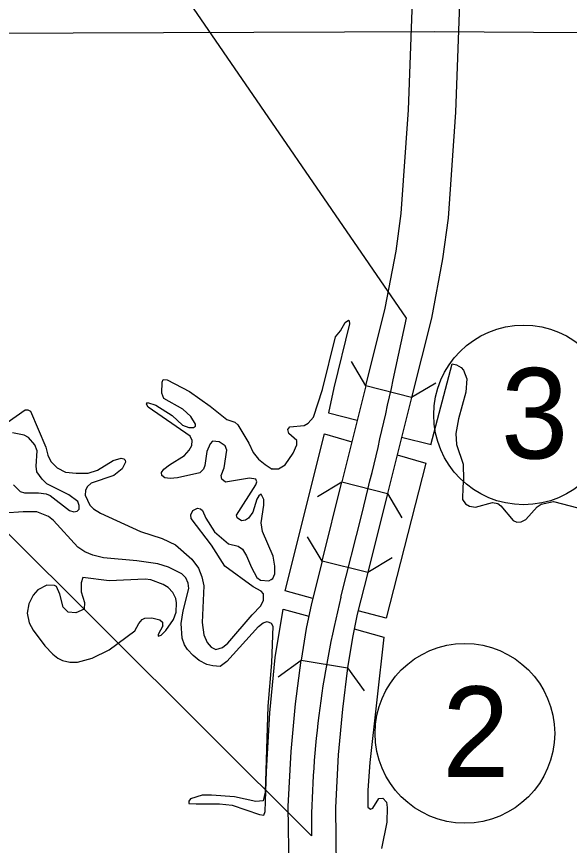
# Model space of a CAD drawing. Extents: x 982240 to 1103002, y 974866 to 1054902.
# Drawn here: x 1025635 to 1028568, y 1003474 to 1007871 of the extents above; entities that cross this region are included whole.
import ezdxf

# ---------------------------------------------------------------- set-up
doc = ezdxf.new("R2010")
doc.units = 0
for name, color, linetype in [('15', 7, 'Continuous'), ('35', 7, 'Continuous'), ('37', 7, 'Continuous'), ('5', 7, 'Continuous'), ('9', 7, 'Continuous'), ('Level 8', 7, 'Continuous'), ('R_Draft', 7, 'Continuous')]:
    doc.layers.add(name, color=color, linetype=linetype)

msp = doc.modelspace()

# ---------------------------------------------------------------- linework, layer by layer
at = {"layer": '15'}
for p, q in [((1027730.2, 1005850.2), (1027488, 1005912.1)), ((1027360.4, 1005402.5), (1027602.6, 1005340.5)), ((1027498, 1004922.3), (1027255.4, 1004983)), ((1027144.1, 1004456.7), (1027390.8, 1004416.4))]:
    msp.add_line(p, q, dxfattribs=at)
for points in [[(1027488, 1005912.1), (1027591.2, 1006324.5), (1027648, 1006626.3), (1027675.6, 1006826.9), (1027714.1, 1007377.1), (1027837.7, 1010743.3), (1027884.1, 1012159.8), (1027883.1, 1012543.8), (1027847.3, 1013534.7), (1027848.2, 1013935.1), (1027894.2, 1014987.8), (1027946.2, 1016469.3)], [(1028196.1, 1016460.3), (1028144, 1014978), (1028098.2, 1013929.3), (1028097.3, 1013538.9), (1028133.1, 1012548.6), (1028134.1, 1012156), (1028087.6, 1010734.6), (1027963.8, 1007363.8), (1027924.4, 1006801.1), (1027894.8, 1006586.1), (1027835.5, 1006271), (1027730.2, 1005850.2)], [(1027488, 1005912.1), (1027360.4, 1005402.5)], [(1027730.2, 1005850.2), (1027602.6, 1005340.5)], [(1027255.4, 1004983), (1027360.4, 1005402.5)], [(1027602.6, 1005340.5), (1027498, 1004922.3)], [(1027255.4, 1004983), (1027198.9, 1004757.3), (1027170.8, 1004624.2), (1027144.1, 1004456.7)], [(1027498, 1004922.3), (1027442.6, 1004701.1), (1027416.6, 1004578.1), (1027390.8, 1004416.4)], [(1027756.9, 999682.4), (1027748.8, 999907.5), (1027717.7, 1000195.3), (1027673, 1000479.3), (1027540.7, 1001071.6), (1027269.7, 1002010.1), (1027208.3, 1002274.5), (1027183.4, 1002408.2), (1027119.6, 1002835), (1027081.4, 1003344.1), (1027076.2, 1003680.1), (1027091.5, 1003973.3), (1027115.3, 1004225.1), (1027144.1, 1004456.7)], [(1027390.8, 1004416.4), (1027363.8, 1004197.9), (1027340.9, 1003955), (1027326.3, 1003675.5), (1027331.2, 1003355.4), (1027368.2, 1002862.9), (1027430, 1002449.6), (1027453.1, 1002325.7), (1027511.7, 1002073.1), (1027783, 1001133.6), (1027918.7, 1000526.1), (1027965.6, 1000228.2), (1027998.3, 999925.5), (1028006.7, 999691.4)]]:
    msp.add_lwpolyline(points, dxfattribs=at)
at = {"layer": '35'}
for p, q in [((1027059.2, 1004824.2), (1027267.9, 1005657.6)), ((1027267.9, 1005657.6), (1027413.8, 1005615.5)), ((1027677.6, 1005640.1), (1027833.6, 1005600.9)), ((1027654.2, 1005546.4), (1027806, 1005502.9)), ((1027205.8, 1004784.6), (1027059.2, 1004824.2)), ((1027048.8, 1004727.8), (1027184.7, 1004689.9)), ((1027595.6, 1004679.1), (1027447.1, 1004719.3)), ((1027425.9, 1004622.5), (1027583.3, 1004578.5))]:
    msp.add_line(p, q, dxfattribs=at)
for points in [[(1026988.2, 1005473.1), (1026990.2, 1005472.3), (1027025.2, 1005472.1), (1027059.8, 1005494), (1027102.5, 1005555.2), (1027121.5, 1005598.8), (1027121, 1005622.9), (1027079, 1005659), (1027073.6, 1005680), (1027085.2, 1005694.3), (1027160.2, 1005702.1), (1027182, 1005713.6), (1027210.3, 1005746.4), (1027257, 1005893), (1027327.7, 1006172.6), (1027353, 1006204.3), (1027379, 1006249.1), (1027395.8, 1006260.5), (1027399.9, 1006256.6), (1027401.2, 1006240.5), (1027317.9, 1005902.4), (1027289.9, 1005769.3), (1027442.6, 1005730.9)], [(1026750.2, 1005571.4), (1026740.8, 1005593.7), (1026709.2, 1005616), (1026675.1, 1005619.2), (1026661.4, 1005604.9), (1026644.3, 1005563.3), (1026634, 1005489.8), (1026626.5, 1005469.6), (1026606.9, 1005450.1), (1026488.2, 1005424.2), (1026450.2, 1005421.3), (1026422.1, 1005424.7), (1026405.8, 1005436.3), (1026403.4, 1005453.3), (1026416.1, 1005469.7), (1026445.6, 1005493.4), (1026525.6, 1005543.5), (1026551, 1005571.2), (1026565.4, 1005596.6), (1026565.8, 1005621.7), (1026555.3, 1005644.5), (1026332.3, 1005799.9), (1026324, 1005814.7), (1026329.8, 1005823.9), (1026373.2, 1005809.9), (1026459.6, 1005754.7), (1026515.9, 1005703.8), (1026549.2, 1005691.5), (1026574.3, 1005691.1), (1026584.1, 1005698.4), (1026584.9, 1005708.4), (1026559.9, 1005750), (1026516.9, 1005789.1), (1026415.4, 1005846), (1026405.8, 1005872.8), (1026407.4, 1005932.1), (1026413.1, 1005945.2), (1026434.2, 1005943.7), (1026551.8, 1005882.3), (1026661.8, 1005804.6), (1026750.6, 1005733.4), (1026793, 1005719.3), (1026809.4, 1005705.7), (1026867.7, 1005607.7), (1026889.9, 1005558), (1026918.8, 1005522.6), (1026953.5, 1005494.3)], [(1025584.8, 1005718.2), (1025679.5, 1005785.6), (1025694.5, 1005784.9), (1025708.7, 1005778.3), (1025790.2, 1005586.5), (1025801.2, 1005544.6), (1025817, 1005510.9), (1025849.9, 1005476.5), (1025894.5, 1005454.5), (1025950.7, 1005448.8)], [(1025618.5, 1005386.8), (1025654.4, 1005352.5), (1025677.6, 1005344), (1025751.7, 1005344.8), (1025790.9, 1005339.7), (1025812.2, 1005330.1), (1025915.2, 1005250.2), (1025939.4, 1005243.8), (1025956.3, 1005248.2), (1025966.1, 1005258.5), (1025967.7, 1005276.6), (1025959.2, 1005298.4), (1025912.3, 1005333.5), (1025795.7, 1005392.9), (1025770.1, 1005417.4), (1025743.1, 1005456.9), (1025739.4, 1005487), (1025743.6, 1005568.3), (1025731.8, 1005600.2), (1025697.9, 1005638.5), (1025675.6, 1005650), (1025613.2, 1005662.6)], [(1026946.5, 1005309.1), (1026932.9, 1005337.9), (1026920, 1005329.6), (1026909.4, 1005310.3), (1026888, 1005241.5), (1026865.7, 1005210.9), (1026849.9, 1005200.5), (1026827.9, 1005197), (1026805.5, 1005211.5), (1026801.2, 1005225.4), (1026904.7, 1005387.4), (1026910.3, 1005403.6), (1026905, 1005416.5), (1026869.8, 1005422.7), (1026743.4, 1005400.8), (1026723.5, 1005416.8), (1026719.5, 1005436.7), (1026735.4, 1005476.5), (1026750.2, 1005571.4)], [(1025950.7, 1005448.8), (1026013.8, 1005449.2), (1026064.5, 1005465.5), (1026147.5, 1005515.6), (1026190.3, 1005528.6), (1026204.4, 1005525.9), (1026211.6, 1005518.1), (1026211.8, 1005507), (1026194.6, 1005471.5), (1026151.4, 1005436.4), (1026031, 1005396.4), (1026008.5, 1005376.9), (1026000.9, 1005356.6), (1025999.5, 1005331.5), (1026022.7, 1005279.9), (1026043.2, 1005260.3), (1026080.8, 1005237.1), (1026292.5, 1005138.7), (1026406.5, 1005102.2), (1026478.4, 1005068.7), (1026564.3, 1004992.5), (1026599.5, 1004945.1), (1026617.6, 1004898.4), (1026628.7, 1004850.5), (1026620.1, 1004657.6), (1026627.7, 1004590.6), (1026645.7, 1004549.9), (1026666.3, 1004525.2), (1026692.6, 1004512.8), (1026727.4, 1004524), (1026755.3, 1004547.9), (1026885.5, 1004697)], [(1026953.5, 1005494.3), (1026990.1, 1005471.1)], [(1026984.7, 1004885), (1026994.3, 1004890.8), (1027005.7, 1004915.1), (1027005.8, 1004956.3), (1026996.5, 1005009.2), (1026940.4, 1005140.4), (1026933.3, 1005186.4), (1026947.2, 1005279), (1026946.5, 1005309.1)], [(1026669.4, 1005067.8), (1026560.3, 1005208.1), (1026559.9, 1005228.2), (1026570.4, 1005251.5), (1026595.1, 1005264.1), (1026610.2, 1005260.5), (1026621.5, 1005250.7), (1026638.4, 1005211), (1026684.8, 1005138.6)], [(1026917.6, 1004635.1), (1026751, 1004449.5), (1026715.7, 1004424.1), (1026676.6, 1004426.1), (1026643.3, 1004434.4), (1026602.7, 1004455.5), (1026571.1, 1004480.9), (1026541.3, 1004513.3), (1026525.7, 1004538), (1026513.9, 1004573.9), (1026508.1, 1004651), (1026518.5, 1004719.5), (1026547.9, 1004837.6), (1026545.2, 1004865.6), (1026533.5, 1004893.4), (1026511, 1004915), (1026441.1, 1004950.5), (1026384.6, 1004968.2), (1026273, 1004984.7), (1026096.3, 1004999.6), (1026039.9, 1005013.3), (1025996.4, 1005031.4), (1025959.8, 1005055.6), (1025830.2, 1005198.1), (1025803.7, 1005218.5), (1025743, 1005244.2), (1025669.9, 1005243.5), (1025568.9, 1005236.1)], [(1026684.8, 1005138.6), (1026759.3, 1005074), (1026810, 1005061.1), (1026833.4, 1005045.6), (1026855.2, 1005011), (1026880.7, 1004948.3), (1026909, 1004895.8), (1026928.4, 1004881.2), (1026973.5, 1004878.3), (1026984.7, 1004885)], [(1026885.5, 1004697), (1026930.4, 1004745.2), (1026945.7, 1004775.7), (1026944, 1004808.8), (1026931.6, 1004823.5), (1026890, 1004846.6), (1026739.2, 1004955.5), (1026669.4, 1005067.8)], [(1026385.2, 1004592.9), (1026385.4, 1004584.9), (1026401.3, 1004589.3), (1026425.8, 1004615), (1026467.5, 1004673.1), (1026480.6, 1004711.6), (1026483.5, 1004760.8), (1026479, 1004783.8), (1026463.2, 1004815.5), (1026439.6, 1004842.1), (1026412.1, 1004858.5), (1026346.4, 1004884), (1026316.3, 1004887.3), (1026125.2, 1004877.9), (1025986.5, 1004895.7), (1025977.1, 1004867.4), (1025978.2, 1004820.2), (1025994.6, 1004763.4), (1025993.4, 1004727.3), (1025949.8, 1004707.2), (1025907.6, 1004712.2), (1025881.9, 1004737.7), (1025864.3, 1004807.5), (1025847.3, 1004848.3), (1025836.2, 1004853), (1025796.1, 1004855.1), (1025747.6, 1004829.9), (1025723.2, 1004801.2), (1025700.2, 1004756.5), (1025690.3, 1004706.1), (1025701.5, 1004655.2), (1025723.4, 1004616.6), (1025785.5, 1004533.7), (1025826.6, 1004488.5), (1025853.1, 1004467.1), (1025878.4, 1004455.6), (1025917.7, 1004446.5), (1025957.8, 1004445.5), (1026036.4, 1004467.4), (1026125.6, 1004512.6), (1026262.5, 1004612.1), (1026283.6, 1004651.8), (1026300.2, 1004673.2), (1026316.1, 1004679.6), (1026352.1, 1004681.5), (1026394.4, 1004670.4), (1026409.7, 1004657.7), (1026408.3, 1004634.6)], [(1026549.5, 1003697.3), (1026587.7, 1003694.1), (1026711.9, 1003695), (1026779.1, 1003688.6), (1026923.6, 1003637.8), (1026946.7, 1003634.3), (1026954.3, 1003653.6), (1026960.4, 1003866.4), (1026978.2, 1004177.9), (1027006.5, 1004471.6), (1027048.8, 1004727.8)], [(1026917.6, 1004635.1), (1026943.2, 1004654.8), (1026964.1, 1004662.3), (1026986.3, 1004653.8), (1026994.7, 1004637.9), (1026987.2, 1004443), (1026967.4, 1004212.8), (1026953.9, 1003755.9), (1026942.9, 1003710.5), (1026903.9, 1003707.6), (1026790.2, 1003732), (1026668.7, 1003741.2), (1026618.7, 1003740), (1026558, 1003720.5), (1026548.2, 1003709.3), (1026549.5, 1003697.3)], [(1026410.2, 1004639.7), (1026385.2, 1004592.9)]]:
    msp.add_lwpolyline(points, dxfattribs=at)
at = {"layer": '37'}
for points in [[(1027488, 1005912.1), (1027411.5, 1006041.2)], [(1027859.2, 1005926.7), (1027730.2, 1005850.2)], [(1027231.4, 1005326), (1027360.4, 1005402.5)], [(1027602.6, 1005340.5), (1027679.1, 1005211.5)], [(1027255.4, 1004983), (1027178.3, 1005111.7)], [(1027626.6, 1004999.5), (1027498, 1004922.3)], [(1027022.3, 1004369.2), (1027144.1, 1004456.7)], [(1027390.8, 1004416.4), (1027478.4, 1004294.6)]]:
    msp.add_lwpolyline(points, dxfattribs=at)
at = {"layer": '5'}
msp.add_lwpolyline([(1018616.9, 1007729), (1022575.1, 1007772.1), (1027854.3, 1007791.2), (1029160.4, 1007783.8)], dxfattribs=at)
at = {"layer": '9'}
for points in [[(1027833, 1005598.6), (1027946.3, 1006028.7)], [(1027946.3, 1006028.7), (1027968.4, 1006023.2), (1027992.8, 1006009.7), (1028006.1, 1005996), (1028023.2, 1005950.2), (1028018.9, 1005878.9), (1027979.1, 1005736.5), (1027964.8, 1005658.9), (1027968.1, 1005601.7), (1028003.6, 1005497.2), (1028006.5, 1005414), (1028004.4, 1005395.4)], [(1027806, 1005502.9), (1027595.6, 1004679.1)], [(1028004.4, 1005395.4), (1028002.2, 1005376.8), (1028000.8, 1005308.6), (1028017.3, 1005285.9), (1028038.6, 1005274.3), (1028068.8, 1005269), (1028160.4, 1005293.2), (1028188.6, 1005288.9), (1028203.9, 1005276.2), (1028268.8, 1005198.4), (1028289.1, 1005188.9), (1028312.1, 1005190.4), (1028335.8, 1005204), (1028397.4, 1005270.7), (1028418.1, 1005284.2), (1028482.7, 1005298.6), (1028693.8, 1005244.6)], [(1027583.3, 1004578.5), (1027508.5, 1003913.4)], [(1027508.5, 1003913.4), (1027497.8, 1003767.7), (1027498.9, 1003676.4), (1027512.2, 1003666.7), (1027525.1, 1003672), (1027557, 1003723.9), (1027578, 1003724.4), (1027597.5, 1003703.8), (1027601.2, 1003674.8), (1027599.9, 1003597.5), (1027571.1, 1003457.3)]]:
    msp.add_lwpolyline(points, dxfattribs=at)
at = {"layer": 'Level 8'}
for p, q in [((1027633.1, 1005943.6), (1027704.4, 1006271.8)), ((1027355.7, 1004790.4), (1027465.9, 1005229.6))]:
    msp.add_line(p, q, dxfattribs=at)
for centre, radius, start, end in [((1005237.3, 1010809.6), 22918.3, 345.90833, 347.74166), ((1032407.6, 1003522.2), 5208.7, 165.9083, 179.9656)]:
    msp.add_arc(centre, radius, start, end, dxfattribs=at)
at = {"layer": 'R_Draft'}
for p, q in [((1027704.4, 1006271.8), (1017029.4, 1021793.7)), ((1027198.9, 1003525.3), (1016573.4, 1014109.3))]:
    msp.add_line(p, q, dxfattribs=at)
for centre in [(1028325, 1005758), (1028013.1, 1004068.8)]:
    msp.add_circle(centre, 476.6, dxfattribs=at)

# ---------------------------------------------------------------- texts
for s, p in [('3', (1028204.7, 1005526.6)), ('2', (1027892.9, 1003837.4))]:
    msp.add_text(s, height=480, dxfattribs=at).set_placement(p)

doc.saveas('drawing.dxf')
